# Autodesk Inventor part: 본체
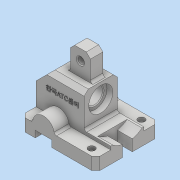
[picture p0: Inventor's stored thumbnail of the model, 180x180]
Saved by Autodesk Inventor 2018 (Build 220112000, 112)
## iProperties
Created: 2022-08
Part Number: 본체
Material: 일반
Document SubType Name: Modeling
Designer: 강의실04
Density: 1 g/cm^3
Appearance: 기본값
Author: 강의실04
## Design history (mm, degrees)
sketch "스케치1"
  geometry: L1 (-45, 38)-(45, 38); L2 (45, 38)-(45, -38); L3 (45, -38)-(-45, -38); L4 (-45, -38)-(-45, 38); 3 further points
  constraints: 8 end point, 2 midpoint, 2 parallel, 1 horizontal, 1 horizontal alignment, 1 perpendicular, 1 vertical alignment
  dimensions: "d0" = 76 distance of L1.end L2.end; "d1" = 90 distance of L1.start L1.end
extrude "돌출1" new body sketch "스케치1" distance "d2" = 15; taper "d3" = 0 deg
sketch "스케치2"
  geometry: L1 (-45, 15)-(45, 15) reference; L2 (45, 15)-(45, 42); L3 (45, 42)-(27, 60); L4 (27, 60)-(-13, 60); L5 (-13, 60)-(-13, 19); L6 (-13, 19)-(-45, 19); L7 (-45, 19)-(-45, 15); L8 (-45, 0)-(-45, 15) reference; 1 further point
  constraints: 12 end point, 3 perpendicular, 2 vertical
  dimensions: "d5" = 45 deg angle of L3 L4; "d6" = 18 distance from line of L3.end L2; "d7" = 32 distance between parallel lines of L8 L5; "d8" = 4 distance of L6.end L1.start; "d22" = 45 distance between parallel lines of L1 L4
extrude "돌출2" join sketch "스케치2" stored distance "d9" = 40; taper "d10" = 0 deg
sketch "스케치3"
  geometry: L1 (27, 60)-(-13, 60) reference; L2 (16, 60)-(16, 90); L3 (16, 90)-(-8, 90); L4 (-8, 90)-(-8, 60); L5 (-13, 60)-(-13, 19) reference; 1 further point
  constraints: 6 end point, 3 perpendicular, 2 point on line
  dimensions: "d11" = 5 distance between parallel lines of L5 L4; "d12" = 24 distance of L2.end L3.end; "d13" = 30 distance between parallel lines of L1 L3
extrude "돌출3" join sketch "스케치3" stored distance "d14" = 15; taper "d15" = 0 deg
chamfer "모따기1" distance "d16" = 5; stored, may be unused: second distance "d17" = 2, angle "d18" = 45 deg
sketch "스케치4"
  geometry: L1 (45, 0)-(-45, 0) reference; L2 (8, 85)-(8, 60) reference; C1 r 4 at (-4, 77); 1 further point
  constraints: 1 centre point
  dimensions: "d23" = 8 diameter of C1; "d24" = 77 distance from line of L1 C1.centre; "d25" = 12 distance from line of C1.centre L2
extrude "돌출4" cut sketch "스케치4" extent not by distance; stored distance "d26" = 15; taper "d27" = 0 deg
node "작업 평면2"
sketch "스케치5"
  geometry: L1 (19, 58)-(19, -18) reference; C1 r 29 at (-23, 20); 2 further points
  constraints: 1 centre point, 1 horizontal alignment, 1 midpoint
  dimensions: "d29" = 58 diameter of C1; "d30" = 42 distance from line of L1 C1.centre
extrude "돌출5" cut sketch "스케치5" distance "d31" = 18; taper "d32" = 0 deg
sketch "스케치6"
  geometry: L1 (-19, 32)-(0, 32); L2 (0, 32)-(0, 44); L3 (0, 44)-(-19, 44); L4 (-19, 44)-(-19, 32); L5 (0, 76)-(0, 0) reference; 3 further points
  constraints: 8 end point, 2 midpoint, 2 parallel, 1 collinear, 1 horizontal, 1 horizontal alignment, 1 perpendicular
  dimensions: "d33" = 12 distance of L1.end L2.end; "d34" = 19 distance of L2.end L3.end
extrude "돌출6" cut sketch "스케치6" distance "d35" = 18; taper "d36" = 0 deg
sketch "스케치7"
  geometry: L1 (0, 15)-(90, 15) reference; L2 (0, 0)-(0, 15) reference; C1 r 13 at (27, 15); 1 further point
  constraints: 1 centre point, 1 point on line
  dimensions: "d37" = 27 distance from line of L2 C1.centre; "d38" = 26 diameter of C1
extrude "돌출7" join sketch "스케치7" stored distance "d39" = 18; taper "d40" = 0 deg
fillet "모깎기1" dims "d41" = 3
sketch "스케치8"
  geometry: L1 (17, 8)-(37, 8); L2 (37, 8)-(37, 0); L3 (37, 0)-(17, 0); L4 (17, 0)-(17, 8); L5 (90, 0)-(0, 0) reference; A1 r 13 centre (27, 15) between (39.769, 17.438) and (14.231, 17.438) reference; 2 further points
  constraints: 8 end point, 2 parallel, 1 collinear, 1 horizontal, 1 midpoint, 1 perpendicular, 1 vertical alignment
  dimensions: "d42" = 20 distance of L2.end L3.end; "d43" = 8 distance of L3.end L1.start
extrude "돌출8" cut sketch "스케치8" extent not by distance; stored distance "d44" = 18; taper "d45" = 0 deg
sketch "스케치9"
  geometry: L1 (45, -38)-(45, -20) reference; L2 (13, -20)-(13, 20) reference; L3 (-2.284, -38)-(45, -38) reference; 2 further points
  dimensions: "d46" = 13 distance from line of L1 point (32, -30); "d47" = 8 distance from line of L3 point (32, -30)
sketch "스케치10"
  geometry: L1 (45, 20)-(45, 38) reference; L2 (45, 38)-(-2.284, 38) reference; 3 further points
  dimensions: "d48" = 13 distance from line of L1 point (32, 30); "d49" = 8 distance from line of point (32, 30) L2
hole "구멍1" sketch "스케치10" at (32, 30), (32, -30) diameter "d50" = 4.5; stored, may be unused: countersink angle "d54" = 90 deg, drill point angle "d56" = 118 deg; dims "d51" = 6, "d52" = 8, "d53" = 4.4, "d55" = 8
sketch "스케치11"
  geometry: L1 (19, 26)-(19, 14) reference; L2 (19, -18)-(19, 58) reference; 3 further points
  constraints: 1 horizontal alignment, 1 midpoint
  dimensions: "d57" = 42 distance from line of L2 point (-23, 20)
hole "구멍2" sketch "스케치11" at (-23, 20) diameter "d58" = 20; stored, may be unused: countersink angle "d62" = 90 deg, drill point angle "d64" = 118 deg; dims "d59" = 6, "d60" = 29, "d61" = 7, "d63" = 8
chamfer "모따기2" distance "d65" = 5; stored, may be unused: second distance "d66" = 2, angle "d67" = 45 deg
sketch "스케치12"
  geometry: L1 (13, 19)-(13, 60) reference; L2 (13, 60)-(-27, 60) reference; 2 further points
  constraints: 1 other
  dimensions: "d68" = 26 distance from line of L1 point (-13, 42); "d69" = 18 distance from line of L2 point (-13, 42)
extrude "돌출9" join sketch "스케치12" distance "d70" = 0.5; taper "d71" = 0 deg
fillet "모깎기2" dims "d72" = 3
fillet "모깎기3" dims "d73" = 3
chamfer "모따기3" distance "d74" = 5; stored, may be unused: second distance "d75" = 2, angle "d76" = 45 deg
chamfer "모따기4" distance "d77" = 1; stored, may be unused: second distance "d78" = 2, angle "d79" = 45 deg
chamfer "모따기5" distance "d80" = 5; stored, may be unused: second distance "d81" = 2, angle "d82" = 45 deg
chamfer "모따기6" distance "d83" = 1; stored, may be unused: second distance "d84" = 2, angle "d85" = 45 deg
chamfer "모따기7" distance "d86" = 1; stored, may be unused: second distance "d87" = 2, angle "d88" = 45 deg
node "솔리드1"
mirror "미러1"
other parameters: "d28" = 32
